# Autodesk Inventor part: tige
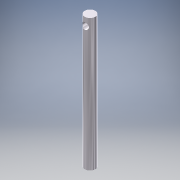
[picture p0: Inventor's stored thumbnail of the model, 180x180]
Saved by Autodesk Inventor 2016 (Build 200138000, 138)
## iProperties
Shininess: 20.0
Angle Display Precision: 2
Document Length Units: 11269
Document Angle Units: 11279
Document Time Units: 11290
Document Mass Units: 11283
Document Length Units Precision: 3
Document Angle Units Precision: 2
Compacted: True
Created: 2002-09
Part Number: tige
Material: Acier inoxydable
Document SubType Name: Modélisation
Designer: administrateur
Mass: 312.164 g
Surface Area: 107.433 cm^2
Volume: 39.0205 cm^3
Density: 8 g/cm^3
Appearance: Métal-AL-6061 (poli)
Density: 0.0
Volumn: 0.0
Area: 0.0
PropertySet Name: Model Information
Control State: 0
Master: False
Checked Out: False
Author: administrateur
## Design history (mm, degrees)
sketch "Esquisse1"
  geometry: C1 r 8 at (0, 0)
  constraints: 1 centre point
  dimensions: "d0" = 16 diameter of C1
extrude "Extrusion1" new body sketch "Esquisse1" distance "d1" = 200; taper "d2" = 0 deg
sketch "Esquisse3"
  geometry: L1 (-8, 200)-(8, 200) reference; C1 r 5 at (0.144, 188)
  constraints: 1 centre point
  dimensions: "d6" = 10 diameter of C1; "d7" = 12 distance from line of L1 C1.centre
extrude "Extrusion3" cut sketch "Esquisse3" stored distance "d8" = 20; taper "d9" = 0 deg
node "Solide1"
node "Corps solides"
node "Corps surfaciques"
